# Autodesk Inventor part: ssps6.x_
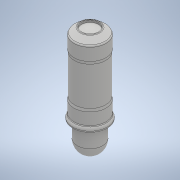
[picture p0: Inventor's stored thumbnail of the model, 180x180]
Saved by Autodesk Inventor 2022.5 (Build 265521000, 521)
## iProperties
Created: 2018-04
Part Number: ssps6.x_
Material: 一般
Document SubType Name: Modeling
Designer: imaocorp
Density: 1 g/cm^3
Appearance: 既定
Sending System: SOLIDWORKS 2016-2016286
MC: AMD64
MC_MODEL: AMD64 Family 21 Model 2 Stepping 0, AuthenticAMD
OS: Windows_NT
FRU: Parasolid Version 28.0, build 224,  7-29-2016
FORMAT: text
GUISE: transmit
KEY: ssps6
FILE: ssps6.x_t
DATE: Wed Apr 25 10:15:56 2018
Author: imaocorp
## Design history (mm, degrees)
feature "Base1"
node "ソリッド1"
